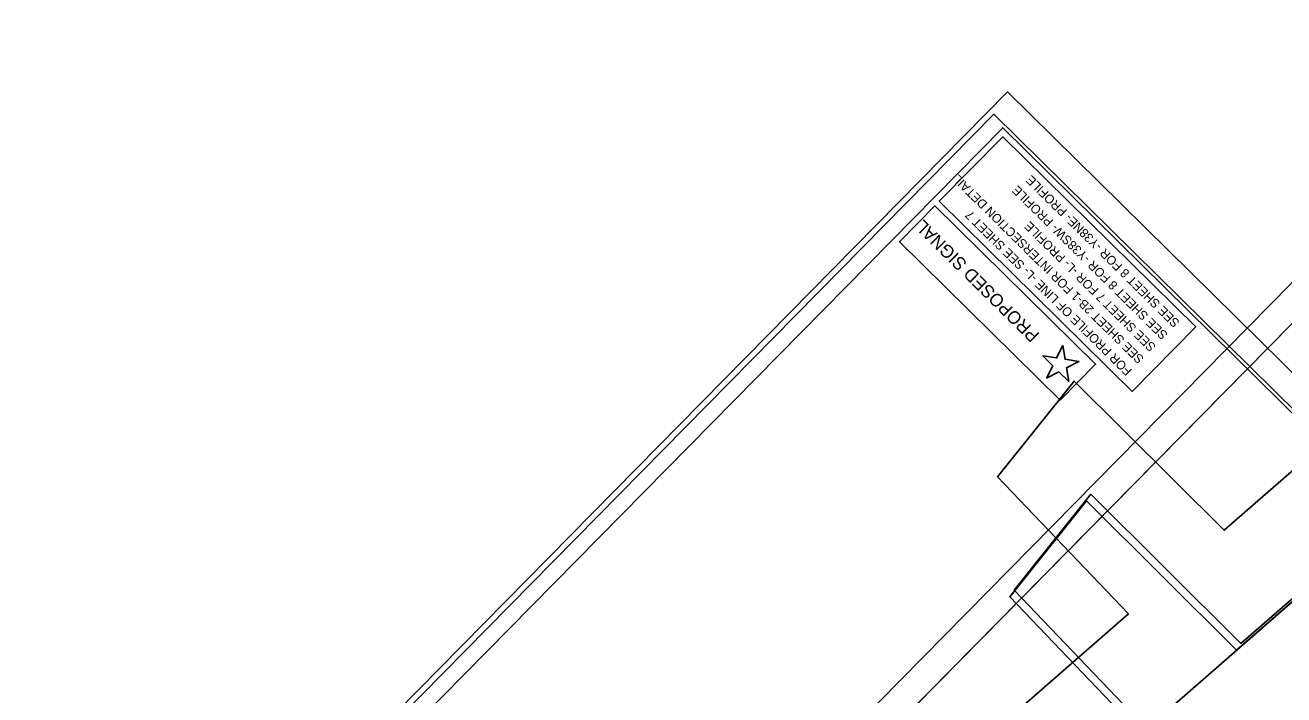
# Model space of a CAD drawing. Extents: x 1265903 to 1267873, y 771347 to 773361.
# Drawn here: x 1265903 to 1266888, y 772837 to 773361 of the extents above; entities that cross this region are included whole.
import ezdxf

# ---------------------------------------------------------------- set-up
doc = ezdxf.new("R2010")
doc.units = 0
for name, color, linetype in [('Exist DTM Spot Elevation Cogo Comment', 7, 'Continuous'), ('Exist DTM Spot Elevation Cogo Elevation', 7, 'Continuous'), ('Exist DTM Spot Elevation Cogo Number', 7, 'Continuous'), ('Exist Utilities Power Pole Cogo Elevation', 7, 'Continuous'), ('Exist Utilities Power UG Cable SUE LOS B Cogo Number', 7, 'Continuous'), ('Exist Utilities Water Meter Cogo Elevation', 7, 'Continuous'), ('Prop Conc 1ft 6in Curb and Gutter', 7, 'Continuous'), ('Prop Conc 4in Sidewalk', 7, 'Continuous'), ('Prop EOT', 7, 'Continuous'), ('Prop Horizontal Alignment Station Label', 7, 'Continuous'), ('Prop Plan Preparation Crest', 7, 'Continuous'), ('Prop Plan Preparation Watershed Post Construction', 7, 'Continuous'), ('Typical Terminator CELL', 7, 'Continuous')]:
    doc.layers.add(name, color=color, linetype=linetype)

msp = doc.modelspace()

# ---------------------------------------------------------------- linework, layer by layer
at = {"layer": 'Exist DTM Spot Elevation Cogo Elevation'}
msp.add_lwpolyline([(1266711.98, 773089.58), (1266719.74, 773081.95), (1266717.95, 773092.68), (1266727.63, 773097.7), (1266716.85, 773099.33), (1266715.06, 773110.08), (1266710.19, 773100.33), (1266699.42, 773101.96), (1266707.18, 773094.31), (1266702.31, 773084.56), (1266711.98, 773089.58)], dxfattribs=at)
at = {"layer": 'Exist DTM Spot Elevation Cogo Number'}
msp.add_lwpolyline([(1266713.07, 773067.39), (1266587.31, 773191.31), (1266614.91, 773219.33), (1266740.68, 773095.41)], close=True, dxfattribs=at)
at = {"layer": 'Exist Utilities Power Pole Cogo Elevation'}
for points in [[(1266816.88, 771715.95), (1267567.86, 772478.14), (1266964.28, 773072.85), (1266841.38, 772965.65), (1266723.84, 773082.29), (1266663.94, 773007.35), (1266766.42, 772900.26), (1266377.83, 772561.31), (1266290.43, 772234.67)], [(1266829.94, 771627.35), (1267580.92, 772389.53), (1266977.34, 772984.25), (1266854.43, 772877.05), (1266736.89, 772993.69), (1266677, 772918.75), (1266779.48, 772811.66), (1266390.89, 772472.71), (1266303.49, 772146.07)], [(1266826.55, 771622.19), (1267577.53, 772384.37), (1266973.95, 772979.08), (1266851.04, 772871.88), (1266733.5, 772988.52), (1266673.61, 772913.58), (1266776.09, 772806.49), (1266387.5, 772467.54), (1266300.09, 772140.9)], [(1266826.55, 771622.19), (1267577.53, 772384.37), (1266973.95, 772979.08), (1266851.04, 772871.88), (1266733.5, 772988.52), (1266673.61, 772913.58), (1266776.09, 772806.49), (1266387.5, 772467.54), (1266300.09, 772140.9)]]:
    msp.add_lwpolyline(points, close=True, dxfattribs=at)
at = {"layer": 'Exist Utilities Power UG Cable SUE LOS B Cogo Number'}
msp.add_lwpolyline([(1266840.58, 771636.43), (1267577.53, 772384.37), (1266973.95, 772979.08), (1266387.5, 772467.54), (1266306.04, 772163.12)], close=True, dxfattribs=at)
at = {"layer": 'Prop Conc 1ft 6in Curb and Gutter'}
for points in [[(1265931.14, 772532.52), (1266999.64, 771479.71), (1267736.59, 772227.64), (1266668.1, 773280.44)], [(1266819.11, 773124.63), (1266668.16, 773273.37), (1266618.42, 773222.89), (1266769.37, 773074.16)]]:
    msp.add_lwpolyline(points, close=True, dxfattribs=at)
at = {"layer": 'Prop Conc 4in Sidewalk'}
msp.add_line((1267092.63, 773360.64), (1265911.05, 772161.45), dxfattribs=at)
at = {"layer": 'Prop EOT'}
msp.add_lwpolyline([(1267847.69, 772121.71), (1266660.96, 773290.98), (1265920.5, 772539.5), (1267107.23, 771370.21)], close=True, dxfattribs=at)
at = {"layer": 'Prop Horizontal Alignment Station Label'}
msp.add_lwpolyline([(1267870.98, 772126.83), (1266671.79, 773308.41), (1265903.26, 772528.42), (1267102.45, 771346.84)], close=True, dxfattribs=at)
at = {"layer": 'Prop Plan Preparation Crest'}
msp.add_lwpolyline([(1266043.92, 772264.22), (1266791.85, 771527.31), (1267844.64, 772595.79), (1267247.35, 773184.3), (1267079.43, 773013.88), (1266928.79, 773162.31)], close=True, dxfattribs=at)
at = {"layer": 'Prop Plan Preparation Watershed Post Construction'}
msp.add_lwpolyline([(1266826.95, 771562.93), (1267809.56, 772560.18), (1267212.27, 773148.7), (1267079.43, 773013.88), (1266928.79, 773162.31), (1266079.01, 772299.87)], close=True, dxfattribs=at)
at = {"layer": 'Typical Terminator CELL'}
msp.add_lwpolyline([(1266826.95, 771562.93), (1267809.56, 772560.18), (1267212.27, 773148.7), (1267079.43, 773013.88), (1266928.79, 773162.31), (1266079.01, 772299.87)], close=True, dxfattribs=at)

# ---------------------------------------------------------------- texts
at = {"layer": 'Exist DTM Spot Elevation Cogo Comment'}
msp.add_text('PROPOSED SIGNAL', height=10, rotation=135.42387, dxfattribs=at).set_placement((1266697.4, 773118.91))
at = {"layer": 'Exist Utilities Water Meter Cogo Elevation'}
for s, p in [('SEE SHEET 2B-1 FOR INTERSECTION DETAIL', (1266779, 773100.18)), ('SEE SHEET 8 FOR -Y38NE- PROFILE', (1266806.95, 773128.44)), ('SEE SHEET 8 FOR -Y38SW- PROFILE', (1266797.63, 773119.02)), ('FOR PROFILE OF LINE -L- SEE SHEET 7', (1266769.68, 773090.76)), ('SEE SHEET 7 FOR -L- PROFILE', (1266788.31, 773109.6))]:
    msp.add_text(s, height=7, rotation=135.31046, dxfattribs=at).set_placement(p)

doc.saveas('drawing.dxf')
